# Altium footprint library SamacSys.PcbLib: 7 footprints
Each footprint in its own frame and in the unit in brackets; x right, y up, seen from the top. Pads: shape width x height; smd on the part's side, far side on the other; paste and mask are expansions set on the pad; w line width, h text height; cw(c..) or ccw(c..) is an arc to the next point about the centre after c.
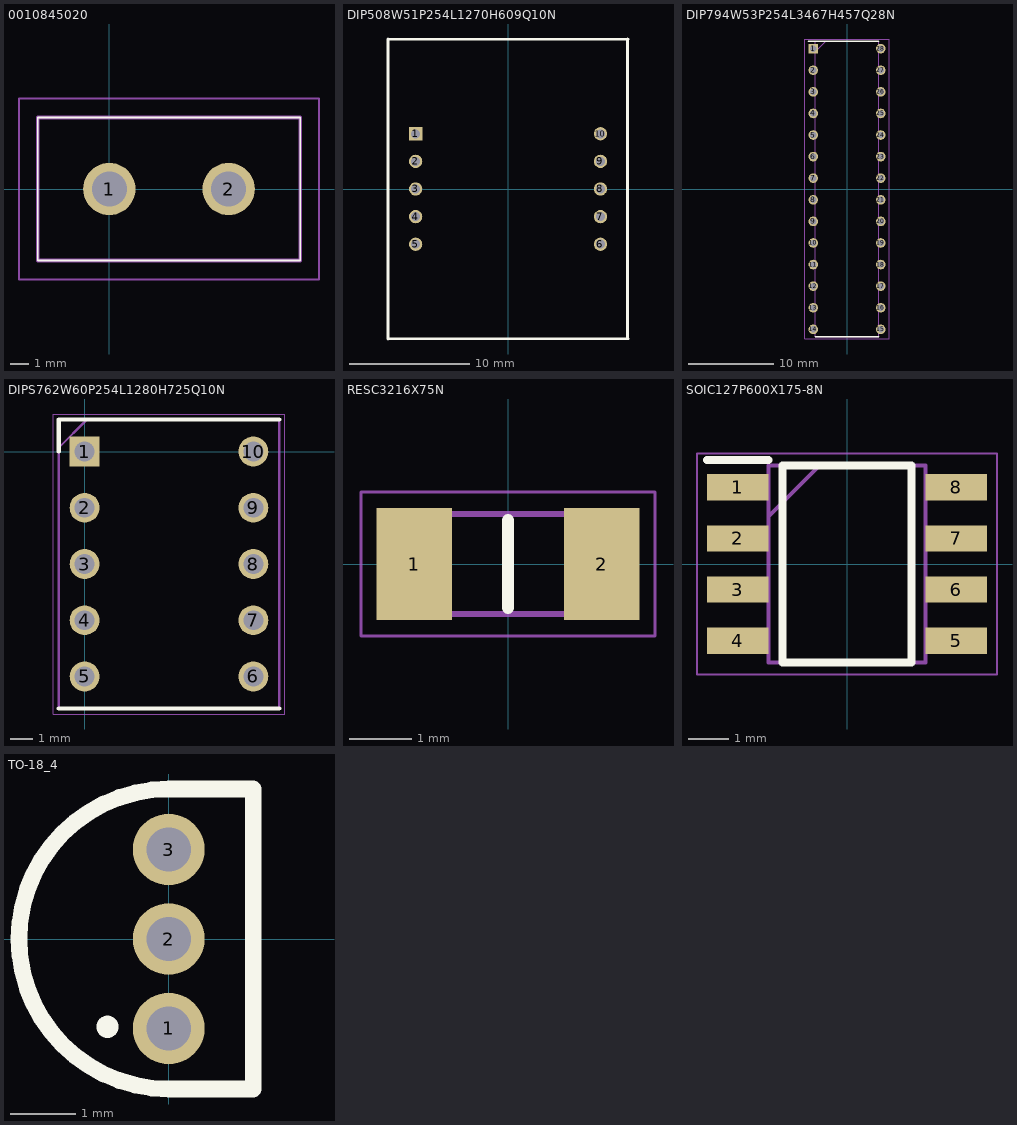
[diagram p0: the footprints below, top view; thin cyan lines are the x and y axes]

## 0010845020 [mm]
pads (2):
  round 2.79 hole 1.86: 1(0,0) 2(6.35,0)
Top Overlay:
  lines w0.1: -3.81,-3.81 10.16,-3.81 10.16,3.81 -3.81,3.81 -3.81,-3.81
Mechanical 13:
  lines w0.2: -3.81,-3.81 10.16,-3.81 10.16,3.81 -3.81,3.81 -3.81,-3.81
Mechanical 15:
  lines w0.1: -4.81,-4.81 11.16,-4.81 11.16,4.81 -4.81,4.81 -4.81,-4.81
3D body "0010845020.stp": height 14.22, standoff -5, extent -3.81,-3.81 10.16,3.81

## DIP508W51P254L1270H609Q10N [mm]
pads (10):
  rect 1.108x1.108 hole 0.75: 1(-7.7,4.6)
  round 1.108 hole 0.75: 2(-7.7,2.3) 3(-7.7,0.003) 4(-7.7,-2.3) 5(-7.7,-4.6) 6(7.7,-4.6) 7(7.7,-2.3) 8(7.7,0.003) 9(7.7,2.3) 10(7.7,4.6)
Top Overlay:
  lines w0.2: -10,-12.492 10,-12.492 ; -10,12.492 10,12.492
  lines w0.254: -10.008,-12.497 -10.008,12.497 ; 9.957,-12.471 9.957,12.497

## DIP794W53P254L3467H457Q28N [mm]
pads (28):
  rect 1.133x1.133 hole 0.733: 1(-3.969,16.51)
  round 1.133 hole 0.733: 2(-3.969,13.97) 3(-3.969,11.43) 4(-3.969,8.89) 5(-3.969,6.35) 6(-3.969,3.81) 7(-3.969,1.27) 8(-3.969,-1.27) 9(-3.969,-3.81) 10(-3.969,-6.35) 11(-3.969,-8.89) 12(-3.969,-11.43) 13(-3.969,-13.97) 14(-3.969,-16.51) 15(3.969,-16.51) 16(3.969,-13.97) 17(3.969,-11.43) 18(3.969,-8.89) 19(3.969,-6.35) 20(3.969,-3.81) 21(3.969,-1.27) 22(3.969,1.27) 23(3.969,3.81) 24(3.969,6.35) 25(3.969,8.89) 26(3.969,11.43) 27(3.969,13.97) 28(3.969,16.51)
Top Overlay:
  lines w0.2: -4.535,17.399 3.746,17.399 ; -3.746,-17.399 3.746,-17.399
Mechanical 13:
  lines w0.1: -3.746,16.129 -2.476,17.399 ; -3.746,-17.399 3.746,-17.399 3.746,17.399 -3.746,17.399 -3.746,-17.399
Mechanical 15:
  lines w0.05: -4.944,-17.649 4.944,-17.649 4.944,17.649 -4.944,17.649 -4.944,-17.649
3D body "ATMEGA328P-PU.stp": height 4.57, standoff -3.5, extent -4.102,-17.335 4.102,17.336

## DIPS762W60P254L1280H725Q10N [mm]
pads (10):
  rect 1.35x1.35 hole 0.9: 1(0,0)
  round 1.35 hole 0.9: 2(0,-2.54) 3(0,-5.08) 4(0,-7.62) 5(0,-10.16) 6(7.62,-10.16) 7(7.62,-7.62) 8(7.62,-5.08) 9(7.62,-2.54) 10(7.62,0)
Top Overlay:
  lines w0.2: -1.165,-11.605 8.785,-11.605 ; -1.165,0 -1.165,1.445 8.785,1.445
Mechanical 13:
  lines w0.1: -1.165,0.175 0.105,1.445 ; -1.165,-11.605 -1.165,1.445 8.785,1.445 8.785,-11.605 -1.165,-11.605
Mechanical 15:
  lines w0.05: -1.415,-11.855 -1.415,1.695 9.035,1.695 9.035,-11.855 -1.415,-11.855

## RESC3216X75N [mm]
pads (2):
  rect 1.2x1.8 smd: 1(-1.5,0) 2(1.5,0)
Top Overlay:
  lines w0.2: 0,-0.7 0,0.7
Mechanical 13:
  lines w0.1: -1.6,-0.8 -1.6,0.8 1.6,0.8 1.6,-0.8 -1.6,-0.8
Mechanical 15:
  lines w0.05: -2.35,-1.15 -2.35,1.15 2.35,1.15 2.35,-1.15 -2.35,-1.15
3D body "CR1206-FX-2200ELF.stp": height 0.75, standoff 0, extent -1.6,-0.8 1.6,0.8

## SOIC127P600X175-8N [mm]
pads (8):
  rect 1.525x0.65 smd: 1(-2.712,1.905) 2(-2.712,0.635) 3(-2.712,-0.635) 4(-2.712,-1.905) 5(2.712,-1.905) 6(2.712,-0.635) 7(2.712,0.635) 8(2.712,1.905)
Top Overlay:
  lines w0.2: -3.475,2.58 -1.95,2.58 ; -1.6,-2.45 1.6,-2.45 1.6,2.45 -1.6,2.45 -1.6,-2.45
Mechanical 13:
  lines w0.1: -1.95,1.18 -0.68,2.45 ; -1.95,-2.45 1.95,-2.45 1.95,2.45 -1.95,2.45 -1.95,-2.45
Mechanical 15:
  lines w0.05: -3.725,-2.75 3.725,-2.75 3.725,2.75 -3.725,2.75 -3.725,-2.75
3D body "NE555DR.stp": height 1.75, standoff 0, extent -3,-2.45 3,2.45

## TO-18_4 [mm]
pads (3):
  round 1.1 hole 0.68: 1(0,-1.372) 2(0,0) 3(0,1.372)
Top Overlay:
  circle w0.254: c-0.94,-1.346 r0.043
  lines w0.254: 0,-2.3 1.2,-2.3 ; 0,2.3 1.275,2.3 1.295,2.28 ; 0.001,-2.3 cw(c0.004,0) 0.001,2.3 ; 1.25,-2.3 1.295,-2.255 ; 1.295,-2.3 1.295,0 1.295,2.3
